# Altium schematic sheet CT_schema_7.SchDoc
size 374 x 245 mm
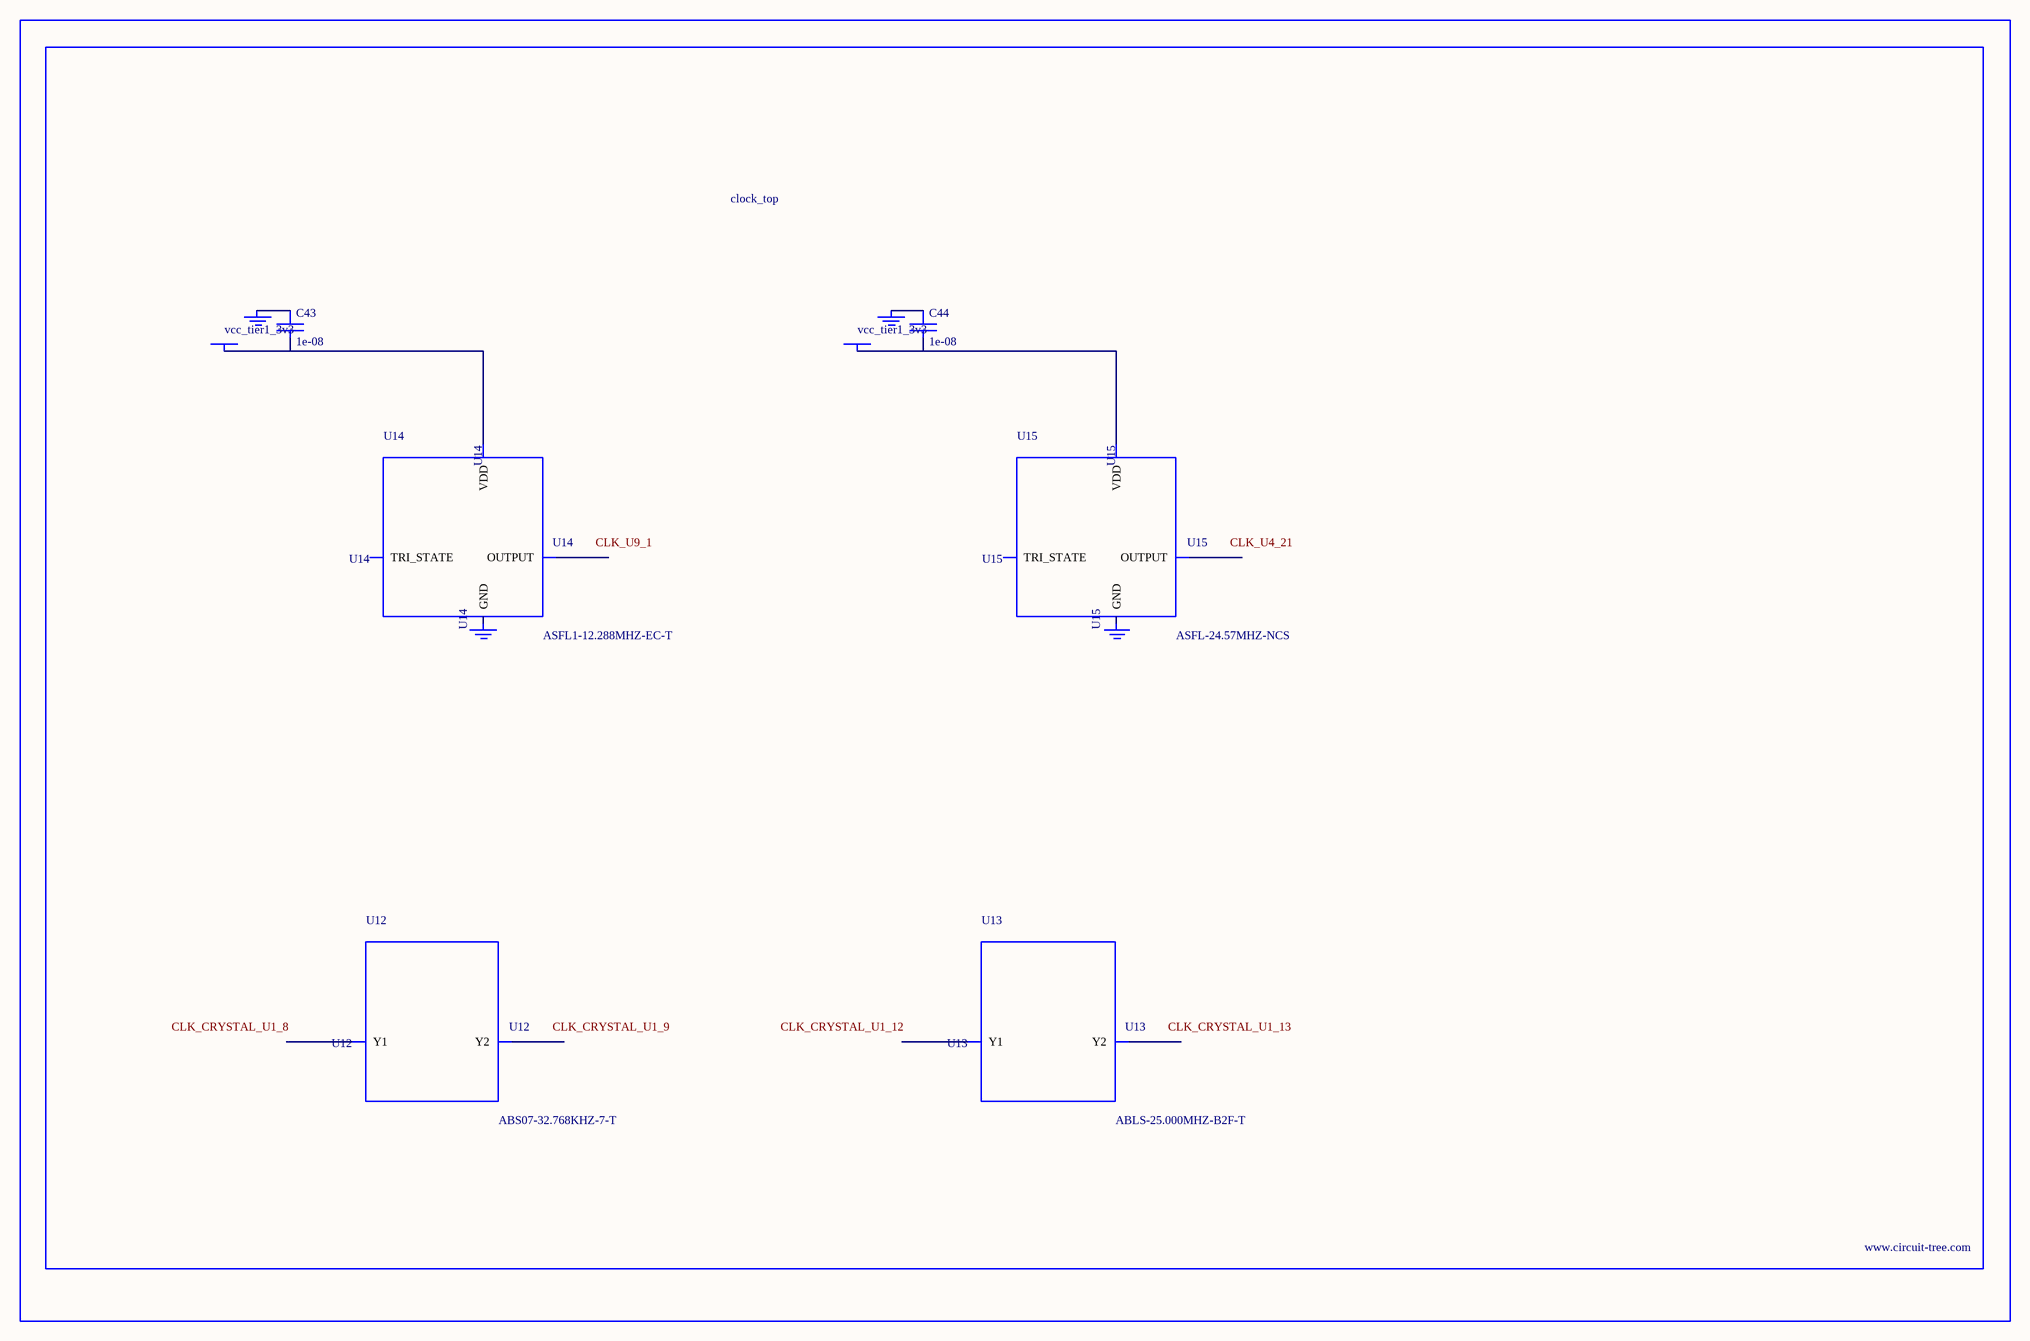
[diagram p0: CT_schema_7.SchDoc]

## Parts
BORDER6  (no value)
C43  1e-08  [C0402]
C44  1e-08  [C0402]
GND_INSTANCE_6_0  (no value)
GND_INSTANCE_6_1  (no value)
GND_INSTANCE_6_2  (no value)
GND_INSTANCE_6_3  (no value)
POWER_INSTANCE_6_0  vcc_tier1_3v3
POWER_INSTANCE_6_1  vcc_tier1_3v3
U12  ABS07-32.768KHZ-7-T  [ABS07-32.768KHZ-7-T]
U13  ABLS-25.000MHZ-B2F-T  [ABLS-25.000MHZ-B2F-T]
U14  ASFL1-12.288MHZ-EC-T  [ASFL1]
U15  ASFL-24.57MHZ-NCS  [ASFL1]

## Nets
NetC43_1: C43.1 GND_INSTANCE_6_0.0(GND)
NetC43_2: C43.2 POWER_INSTANCE_6_0.0(PWR) U14.4(VDD)
NetC44_1: C44.1 GND_INSTANCE_6_2.0(GND)
NetC44_2: C44.2 POWER_INSTANCE_6_1.0(PWR) U15.4(VDD)

Not connected (* = marked no-connect by the designer): GND_INSTANCE_6_1 0(GND); GND_INSTANCE_6_3 0(GND); U12 1(Y1) 2(Y2); U13 1(Y1) 2(Y2); U14 1(TRI_STATE) 2(GND) 3(OUTPUT); U15 1(TRI_STATE) 2(GND) 3(OUTPUT)

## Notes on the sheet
- Labels drawn without touching a wire or pin: CLK_CRYSTAL_U1_8, CLK_CRYSTAL_U1_9, CLK_CRYSTAL_U1_12, CLK_CRYSTAL_U1_13, CLK_U4_21, CLK_U9_1

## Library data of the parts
BORDER6 = BORDER_PAGE6
C43 C44 = C0402C103K3RAC
GND_INSTANCE_6_0-GND_INSTANCE_6_3 = GND
POWER_INSTANCE_6_0 POWER_INSTANCE_6_1 = PWR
